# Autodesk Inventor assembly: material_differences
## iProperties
Shininess: 64.0
Length Units: 11272
Angle Units: 11279
Time Units: 11290
Mass Units: 11286
Length Display Precision: 3
Angle Display Precision: 2
Compacted: True
Part Number: material_differences
Document SubType Name: Assembly
Created: 2005-05
Designer: John Blackburn
Manufacturer: Standard
Standards Organization: Custom
Density: 0.0
Volumn: 0.0
Area: 0.0
PropertySet Name: Model Information
Control State: 0
Master: False
Checked Out: False
Author: John Blackburn
